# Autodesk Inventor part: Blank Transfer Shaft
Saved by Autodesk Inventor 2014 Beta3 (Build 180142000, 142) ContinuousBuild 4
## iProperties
Created: 2011-01
Part Number: Blank Transfer Shaft
Material: Steel
Document SubType Name: Modeling
Designer: Beta-8540w
Density: 1 g/cm^3
Appearance: Steel
CustomPartVersion: 1
Author: Beta-8540w
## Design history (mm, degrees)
sketch "Main Sketch"
  geometry: L1 (0, 0)-(51, 0) reference; L2 (0, 0)-(0, 5); L3 (0, 5)-(10, 5); L4 (10, 5)-(10, 6); L5 (10, 6)-(13, 6); L6 (13, 6)-(13, 12.5); L7 (25, 12.5)-(25, 6); L8 (13, 12.5)-(25, 12.5); L9 (41, 6)-(41, 5); L10 (25, 6)-(41, 6); L11 (51, 5)-(51, 0); L12 (41, 5)-(51, 5)
  constraints: 24 end point, 7 horizontal, 6 vertical
  dimensions: "d3" = 10 diameter of L3 L1 (derived); "d4" = 12 diameter of L5 L1 (derived); "d5" = 25 diameter of L8 L1 (derived); "d6" = 12 diameter of L10 L1 (derived); "d7" = 10 diameter of L12 L1 (derived)
revolve "Revolution1" sketch "Main Sketch" stored, may be unused: angle "d8" = 0 deg
chamfer "Chamfer1" distance "d9" = 0.3; stored, may be unused: second distance "d10" = 0.125, angle "d11" = 45 deg
chamfer "Chamfer2" distance "d12" = 0.3; stored, may be unused: second distance "d13" = 0.125, angle "d14" = 45 deg
body "Solid1"
other parameters: "d0" = 0, "d1" = 0, "d2" = 0
